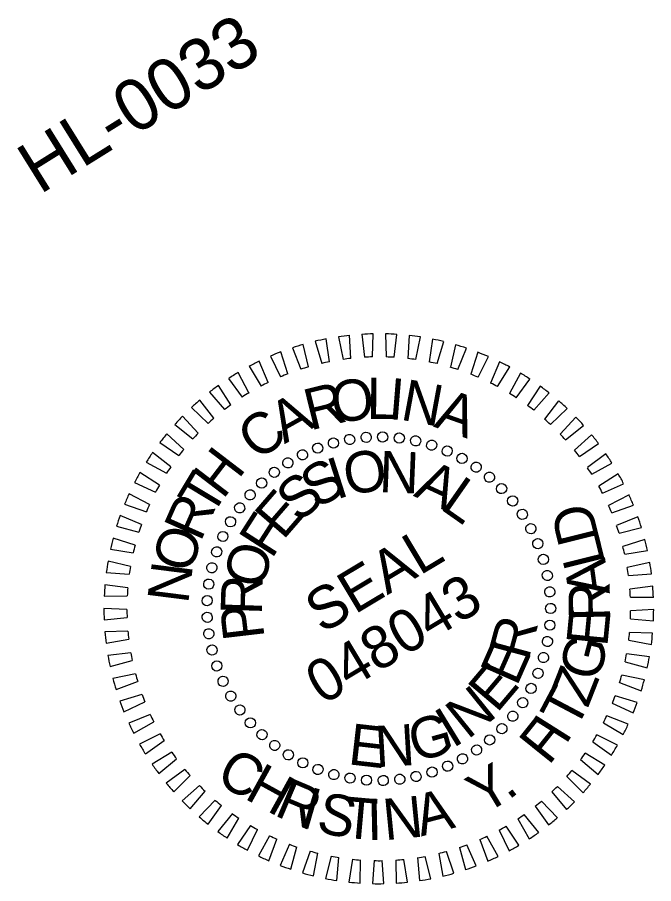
# Model space of a CAD drawing. Extents: x 2045918 to 2047994, y 757573 to 759227.
# Drawn here: x 2047092.2 to 2047184.8, y 759053.8 to 759179.9 of the extents above; entities that cross this region are included whole.
import ezdxf

# ---------------------------------------------------------------- set-up
doc = ezdxf.new("R2010")
doc.units = 0
doc.layers.add('Sheet Data Field CELL', color=7, linetype='Continuous')
doc.layers.add('Sheet PE Seal Cell', color=7, linetype='Continuous')

msp = doc.modelspace()

# ---------------------------------------------------------------- linework, layer by layer
at = {"layer": 'Sheet PE Seal Cell'}
for p, q in [((2047138.94, 759133.41), (2047139.61, 759130.12)), ((2047140.75, 759130.27), (2047140.57, 759133.62)), ((2047142.36, 759133.77), (2047142.74, 759130.44)), ((2047143.89, 759130.48), (2047144.01, 759133.84)), ((2047145.8, 759133.83), (2047145.9, 759130.48)), ((2047147.05, 759130.43), (2047147.45, 759133.76)), ((2047149.23, 759133.6), (2047149.04, 759130.25)), ((2047150.18, 759130.1), (2047150.87, 759133.38)), ((2047134.57, 759129.03), (2047133.82, 759132.31)), ((2047135.56, 759132.76), (2047136.51, 759129.54)), ((2047137.63, 759129.78), (2047137.17, 759133.11)), ((2047152.63, 759133.07), (2047152.16, 759129.75)), ((2047153.28, 759129.5), (2047154.25, 759132.71)), ((2047155.98, 759132.25), (2047155.22, 759128.99)), ((2047131.58, 759128.02), (2047130.56, 759131.22)), ((2047132.24, 759131.82), (2047133.47, 759128.7)), ((2047156.31, 759128.64), (2047157.55, 759131.76)), ((2047159.24, 759131.15), (2047158.2, 759127.96)), ((2047128.69, 759126.76), (2047127.4, 759129.85)), ((2047129.03, 759130.6), (2047130.52, 759127.59)), ((2047159.26, 759127.52), (2047160.76, 759130.52)), ((2047162.39, 759129.77), (2047161.08, 759126.68)), ((2047125.93, 759129.11), (2047127.67, 759126.24)), ((2047162.1, 759126.16), (2047163.86, 759129.02)), ((2047122.96, 759127.35), (2047124.95, 759124.64)), ((2047125.92, 759125.25), (2047124.36, 759128.22)), ((2047165.42, 759128.13), (2047163.84, 759125.16)), ((2047164.82, 759124.55), (2047166.81, 759127.25)), ((2047123.29, 759123.51), (2047121.48, 759126.34)), ((2047168.29, 759126.23), (2047166.47, 759123.41)), ((2047120.16, 759125.35), (2047122.37, 759122.82)), ((2047167.38, 759122.72), (2047169.6, 759125.23)), ((2047120.82, 759121.55), (2047118.78, 759124.21)), ((2047170.98, 759124.09), (2047168.93, 759121.44)), ((2047117.55, 759123.11), (2047119.96, 759120.79)), ((2047169.78, 759120.67), (2047172.21, 759122.99)), ((2047118.53, 759119.39), (2047116.26, 759121.86)), ((2047173.49, 759121.73), (2047171.21, 759119.26)), ((2047115.13, 759120.66), (2047117.74, 759118.55)), ((2047172, 759118.42), (2047174.61, 759120.52)), ((2047116.43, 759117.03), (2047113.96, 759119.31)), ((2047175.78, 759119.16), (2047173.3, 759116.9)), ((2047112.94, 759118.01), (2047115.72, 759116.13)), ((2047174.01, 759115.99), (2047176.8, 759117.86)), ((2047114.54, 759114.51), (2047111.89, 759116.56)), ((2047177.84, 759116.4), (2047175.17, 759114.37)), ((2047110.98, 759115.18), (2047113.91, 759113.55)), ((2047175.8, 759113.4), (2047178.74, 759115.02)), ((2047112.88, 759111.83), (2047110.05, 759113.65)), ((2047179.66, 759113.48), (2047176.83, 759111.68)), ((2047109.27, 759112.2), (2047112.33, 759110.82)), ((2047177.37, 759110.67), (2047180.44, 759112.03)), ((2047111.45, 759109.02), (2047108.48, 759110.58)), ((2047181.22, 759110.41), (2047178.24, 759108.86)), ((2047107.82, 759109.07), (2047110.99, 759107.96)), ((2047178.7, 759107.8), (2047181.87, 759108.9)), ((2047110.27, 759106.09), (2047107.18, 759107.4)), ((2047182.51, 759107.22), (2047179.41, 759105.93)), ((2047106.65, 759105.84), (2047109.9, 759105)), ((2047179.77, 759104.84), (2047183.03, 759105.66)), ((2047109.34, 759103.08), (2047106.15, 759104.11)), ((2047183.52, 759103.93), (2047180.32, 759102.91)), ((2047105.76, 759102.51), (2047109.07, 759101.96)), ((2047180.59, 759101.79), (2047183.9, 759102.33)), ((2047108.68, 759100), (2047105.41, 759100.75)), ((2047184.24, 759100.57), (2047180.97, 759099.83)), ((2047105.16, 759099.12), (2047108.5, 759098.86)), ((2047181.14, 759098.69), (2047184.48, 759098.94)), ((2047108.28, 759096.87), (2047104.96, 759097.34)), ((2047184.67, 759097.15), (2047181.35, 759096.7)), ((2047104.85, 759095.69), (2047108.21, 759095.72)), ((2047181.42, 759095.55), (2047184.77, 759095.51)), ((2047108.16, 759093.72), (2047104.81, 759093.9)), ((2047144.81, 759093.84), (2047144.81, 759093.84)), ((2047184.81, 759093.71), (2047181.46, 759093.54)), ((2047104.84, 759092.25), (2047108.18, 759092.57)), ((2047181.43, 759092.39), (2047184.77, 759092.06)), ((2047108.31, 759090.57), (2047104.95, 759090.46)), ((2047105.13, 759088.82), (2047108.43, 759089.42)), ((2047181.17, 759089.25), (2047184.47, 759088.64)), ((2047184.65, 759090.28), (2047181.3, 759090.39)), ((2047108.72, 759087.44), (2047105.39, 759087.05)), ((2047184.2, 759086.86), (2047180.86, 759087.27)), ((2047105.7, 759085.43), (2047108.94, 759086.31)), ((2047180.64, 759086.14), (2047183.87, 759085.25)), ((2047109.41, 759084.36), (2047106.12, 759083.69)), ((2047106.57, 759082.1), (2047109.72, 759083.26)), ((2047179.85, 759083.09), (2047182.99, 759081.92)), ((2047183.45, 759083.5), (2047180.17, 759084.2)), ((2047110.35, 759081.35), (2047107.14, 759080.4)), ((2047182.42, 759080.22), (2047179.21, 759081.19)), ((2047107.72, 759078.86), (2047110.76, 759080.28)), ((2047178.79, 759080.12), (2047181.82, 759078.68)), ((2047111.55, 759078.44), (2047108.43, 759077.21)), ((2047181.11, 759077.04), (2047177.99, 759078.28)), ((2047109.15, 759075.72), (2047112.05, 759077.4)), ((2047177.49, 759077.25), (2047180.38, 759075.56)), ((2047113, 759075.64), (2047110, 759074.14)), ((2047179.53, 759073.98), (2047176.53, 759075.49)), ((2047110.84, 759072.73), (2047113.59, 759074.65)), ((2047175.94, 759074.5), (2047178.68, 759072.56)), ((2047114.68, 759072.97), (2047111.82, 759071.22)), ((2047112.78, 759069.88), (2047115.35, 759072.03)), ((2047174.16, 759071.9), (2047176.72, 759069.73)), ((2047177.69, 759071.07), (2047174.83, 759072.83)), ((2047116.59, 759070.46), (2047113.89, 759068.47)), ((2047114.96, 759067.22), (2047117.34, 759069.58)), ((2047172.17, 759069.45), (2047174.53, 759067.08)), ((2047175.61, 759068.33), (2047172.92, 759070.32)), ((2047118.71, 759068.12), (2047116.18, 759065.91)), ((2047173.3, 759065.77), (2047170.79, 759067.99)), ((2047117.36, 759064.75), (2047119.53, 759067.31)), ((2047169.97, 759067.19), (2047172.12, 759064.62)), ((2047121.01, 759065.97), (2047118.69, 759063.55)), ((2047170.79, 759063.43), (2047168.47, 759065.86)), ((2047119.96, 759062.5), (2047121.9, 759065.24)), ((2047167.58, 759065.13), (2047169.51, 759062.38)), ((2047123.5, 759064.03), (2047121.39, 759061.42)), ((2047122.75, 759060.48), (2047124.44, 759063.37)), ((2047165.03, 759063.28), (2047166.71, 759060.37)), ((2047168.08, 759061.31), (2047165.98, 759063.93)), ((2047126.14, 759062.31), (2047124.26, 759059.52)), ((2047125.7, 759058.71), (2047127.14, 759061.73)), ((2047162.33, 759061.65), (2047163.76, 759058.62)), ((2047165.19, 759059.43), (2047163.33, 759062.22)), ((2047128.92, 759060.82), (2047127.29, 759057.88)), ((2047128.79, 759057.19), (2047129.96, 759060.33)), ((2047159.5, 759060.27), (2047160.66, 759057.12)), ((2047162.16, 759057.8), (2047160.54, 759060.74)), ((2047131.82, 759059.57), (2047130.45, 759056.51)), ((2047132, 759055.95), (2047132.9, 759059.18)), ((2047156.55, 759059.13), (2047157.44, 759055.89)), ((2047159, 759056.44), (2047157.64, 759059.51)), ((2047134.81, 759058.58), (2047133.71, 759055.41)), ((2047135.3, 759054.99), (2047135.92, 759058.29)), ((2047137.88, 759057.85), (2047137.05, 759054.6)), ((2047152.38, 759054.57), (2047151.57, 759057.82)), ((2047153.53, 759058.25), (2047154.13, 759054.95)), ((2047155.73, 759055.36), (2047154.64, 759058.54)), ((2047138.68, 759054.32), (2047139.01, 759057.66)), ((2047141, 759057.39), (2047140.46, 759054.08)), ((2047142.1, 759053.94), (2047142.15, 759057.29)), ((2047144.15, 759057.2), (2047143.89, 759053.85)), ((2047145.54, 759053.85), (2047145.3, 759057.2)), ((2047147.3, 759057.28), (2047147.33, 759053.92)), ((2047148.97, 759054.06), (2047148.45, 759057.37)), ((2047150.43, 759057.63), (2047150.75, 759054.29))]:
    msp.add_line(p, q, dxfattribs=at)
for radius, start, end in [(40, 96.0801, 98.4437), (40, 91.1486, 93.5122), (40, 86.2171, 88.5807), (40, 81.2856, 83.6492), (40, 105.9431, 108.3067), (40, 101.0116, 103.3752), (40, 76.3541, 78.7177), (40, 71.4226, 73.7862), (40, 110.8746, 113.2382), (40, 66.491, 68.8547), (40, 115.8061, 118.1697), (36.65, 101.2945, 103.0924), (36.65, 96.363, 98.1608), (36.65, 91.4314, 93.2293), (36.65, 86.4999, 88.2978), (36.65, 81.5684, 83.3663), (36.65, 76.6369, 78.4348), (40, 61.5595, 63.9232), (36.65, 106.226, 108.0239), (36.65, 71.7054, 73.5033), (40, 120.7376, 123.1012), (36.65, 111.1575, 112.9554), (36.65, 66.7739, 68.5718), (40, 56.628, 58.9917), (40, 125.6691, 128.0327), (36.65, 116.089, 117.8869), (36.65, 61.8424, 63.6403), (40, 51.6965, 54.0601), (36.65, 121.0205, 122.8184), (36.65, 56.9109, 58.7088), (40, 130.6006, 132.9643), (36.65, 125.952, 127.7499), (36.65, 51.9794, 53.7773), (40, 46.765, 49.1286), (40, 135.5321, 137.8958), (36.65, 130.8835, 132.6814), (36.65, 47.0479, 48.8458), (40, 41.8335, 44.1971), (40, 140.4637, 142.8273), (36.65, 135.815, 137.6129), (36.65, 42.1164, 43.9143), (40, 36.902, 39.2656), (36.65, 140.7465, 142.5444), (40, 145.3952, 147.7588), (36.65, 37.1849, 38.9828), (40, 31.9705, 34.3341), (36.65, 145.678, 147.4759), (40, 150.3267, 152.6903), (36.65, 32.2534, 34.0513), (40, 27.039, 29.4026), (36.65, 150.6095, 152.4074), (36.65, 27.3219, 29.1197), (40, 155.2582, 157.6218), (40, 22.1075, 24.4711), (36.65, 155.541, 157.3389), (36.65, 22.3903, 24.1882), (40, 160.1897, 162.5533), (40, 17.176, 19.5396), (36.65, 160.4725, 162.2704), (36.65, 17.4588, 19.2567), (40, 165.1212, 167.4848), (40, 12.2445, 14.6081), (36.65, 165.404, 167.2019), (36.65, 12.5273, 14.3252), (40, 170.0527, 172.4163), (36.65, 170.3356, 172.1334), (36.65, 7.5958, 9.3937), (40, 7.313, 9.6766), (40, 174.9842, 177.3478), (36.65, 175.2671, 177.065), (40, 2.3815, 4.7451), (36.65, 2.6643, 4.4622), (40, 179.9157, 182.2793), (36.65, 180.1986, 181.9965), (36.65, 357.7328, 359.5307), (40, 357.45, 359.8136), (36.65, 185.1301, 186.928), (40, 184.8472, 187.2108), (36.65, 352.8013, 354.5992), (40, 352.5184, 354.8821), (40, 189.7787, 192.1423), (36.65, 190.0616, 191.8595), (36.65, 347.8698, 349.6677), (40, 347.5869, 349.9506), (36.65, 194.9931, 196.791), (40, 194.7102, 197.0738), (36.65, 342.9383, 344.7362), (40, 342.6554, 345.019), (36.65, 199.9246, 201.7225), (36.65, 338.0068, 339.8047), (40, 199.6417, 202.0054), (40, 337.7239, 340.0875), (36.65, 204.8561, 206.654), (36.65, 333.0753, 334.8732), (40, 204.5732, 206.9369), (40, 332.7924, 335.156), (36.65, 209.7876, 211.5855), (36.65, 328.1438, 329.9417), (40, 209.5047, 211.8684), (36.65, 214.7191, 216.517), (40, 327.8609, 330.2245), (36.65, 323.2123, 325.0102), (40, 214.4363, 216.7999), (36.65, 219.6506, 221.4485), (40, 322.9294, 325.293), (36.65, 318.2808, 320.0787), (40, 219.3678, 221.7314), (36.65, 224.5821, 226.38), (36.65, 313.3493, 315.1471), (40, 317.9979, 320.3615), (40, 224.2993, 226.6629), (36.65, 229.5136, 231.3115), (36.65, 308.4177, 310.2156), (40, 313.0664, 315.43), (40, 229.2308, 231.5944), (36.65, 234.4451, 236.243), (36.65, 303.4862, 305.2841), (40, 308.1349, 310.4985), (36.65, 239.3766, 241.1745), (36.65, 298.5547, 300.3526), (40, 234.1623, 236.5259), (36.65, 244.3082, 246.1061), (36.65, 293.6232, 295.4211), (40, 303.2034, 305.567), (40, 239.0938, 241.4574), (36.65, 249.2397, 251.0376), (36.65, 288.6917, 290.4896), (40, 298.2719, 300.6355), (40, 244.0253, 246.3889), (36.65, 254.1712, 255.9691), (36.65, 259.1027, 260.9006), (36.65, 278.8287, 280.6266), (36.65, 283.7602, 285.5581), (40, 293.3404, 295.704), (40, 248.9568, 251.3204), (36.65, 264.0342, 265.8321), (36.65, 268.9657, 270.7636), (36.65, 273.8972, 275.6951), (40, 253.8883, 256.2519), (40, 283.4773, 285.841), (40, 288.4089, 290.7725), (40, 258.8198, 261.1834), (40, 263.7513, 266.1149), (40, 273.6143, 275.978), (40, 278.5458, 280.9095), (40, 268.6828, 271.0464)]:
    msp.add_arc((2047144.81, 759093.84), radius, start, end, dxfattribs=at)
for centre, major_axis in [((2047142.97, 759118.78), (-0.106, 0.735)), ((2047145.38, 759118.84), (-0.035, 0.742)), ((2047138.21, 759117.96), (-0.245, 0.701)), ((2047140.57, 759118.48), (-0.177, 0.721)), ((2047147.79, 759118.67), (0.037, 0.741)), ((2047150.17, 759118.26), (0.108, 0.734)), ((2047152.5, 759117.63), (0.179, 0.721)), ((2047133.7, 759116.24), (-0.375, 0.64)), ((2047135.91, 759117.21), (-0.312, 0.674)), ((2047154.76, 759116.78), (0.247, 0.7)), ((2047131.59, 759115.06), (-0.435, 0.601)), ((2047156.93, 759115.71), (0.314, 0.673)), ((2047129.6, 759113.69), (-0.491, 0.556)), ((2047158.98, 759114.44), (0.377, 0.639)), ((2047160.91, 759112.97), (0.437, 0.6)), ((2047127.76, 759112.13), (-0.543, 0.506)), ((2047162.68, 759111.33), (0.493, 0.555)), ((2047126.08, 759110.4), (-0.589, 0.452)), ((2047164.28, 759109.52), (0.544, 0.505)), ((2047124.56, 759108.51), (-0.63, 0.393)), ((2047165.7, 759107.57), (0.59, 0.45)), ((2047123.24, 759106.49), (-0.665, 0.33)), ((2047166.93, 759105.49), (0.631, 0.391)), ((2047122.12, 759104.35), (-0.694, 0.264)), ((2047167.95, 759103.3), (0.666, 0.328)), ((2047121.22, 759102.11), (-0.716, 0.196)), ((2047168.76, 759101.02), (0.694, 0.262)), ((2047120.53, 759099.8), (-0.732, 0.126)), ((2047169.34, 759098.68), (0.717, 0.194)), ((2047120.07, 759097.42), (-0.74, 0.055)), ((2047169.69, 759096.29), (0.732, 0.124)), ((2047119.84, 759095.02), (-0.742, -0.017)), ((2047169.81, 759093.88), (0.74, 0.053)), ((2047119.84, 759092.6), (-0.737, -0.088)), ((2047169.7, 759091.46), (0.742, -0.019)), ((2047120.08, 759090.2), (-0.725, -0.159)), ((2047169.35, 759089.07), (0.737, -0.091)), ((2047120.54, 759087.83), (-0.706, -0.228)), ((2047168.77, 759086.73), (0.725, -0.161)), ((2047121.24, 759085.52), (-0.681, -0.296)), ((2047167.98, 759084.45), (0.706, -0.23)), ((2047122.15, 759083.28), (-0.649, -0.36)), ((2047166.96, 759082.25), (0.68, -0.297)), ((2047123.28, 759081.14), (-0.612, -0.421)), ((2047165.74, 759080.17), (0.648, -0.362)), ((2047124.6, 759079.12), (-0.568, -0.478)), ((2047126.12, 759077.24), (-0.519, -0.53)), ((2047164.32, 759078.21), (0.61, -0.423)), ((2047162.72, 759076.4), (0.567, -0.479)), ((2047127.81, 759075.52), (-0.466, -0.578)), ((2047160.95, 759074.76), (0.518, -0.532)), ((2047129.66, 759073.96), (-0.408, -0.62)), ((2047131.65, 759072.59), (-0.346, -0.657)), ((2047159.04, 759073.29), (0.464, -0.579)), ((2047133.76, 759071.42), (-0.281, -0.687)), ((2047154.82, 759070.94), (0.344, -0.658)), ((2047156.99, 759072.01), (0.406, -0.622)), ((2047135.97, 759070.46), (-0.213, -0.711)), ((2047138.27, 759069.71), (-0.144, -0.728)), ((2047152.56, 759070.08), (0.279, -0.688)), ((2047140.63, 759069.2), (-0.073, -0.739)), ((2047143.03, 759068.91), (-0.001, -0.742)), ((2047145.45, 759068.85), (0.071, -0.739)), ((2047147.85, 759069.03), (0.142, -0.729)), ((2047150.23, 759069.44), (0.211, -0.712))]:
    msp.add_ellipse(centre, major_axis=major_axis, ratio=0.999708, dxfattribs=at)

# ---------------------------------------------------------------- texts
at = {"layer": 'Sheet Data Field CELL'}
msp.add_text('HL-0033', height=7.5, rotation=31.918, dxfattribs=at).set_placement((2047095.48, 759154.03))
at = {"layer": 'Sheet PE Seal Cell'}
for s, height, rotation, p in [('O', 6, 6.5508, (2047138.2, 759120.86)), ('L', 6, 359.3506, (2047143, 759121.47)), ('I', 6, 355.3629, (2047146.08, 759121.45)), ('N', 6, 349.5264, (2047147.81, 759121.38)), ('R', 6, 13.8401, (2047134.81, 759119.76)), ('A', 6, 340.5961, (2047152.68, 759120.35)), ('A', 6, 29.3273, (2047131.08, 759117.77)), ('C', 6, 38.2117, (2047127.31, 759115.19)), ('H', 6, 52.5806, (2047122.12, 759109.63)), ('I', 6, 17.7649, (2047138.62, 759109.7)), ('O', 6, 9.375, (2047140.19, 759110.31)), ('N', 6, 357.6615, (2047144.77, 759110.83)), ('S', 6, 31.9248, (2047135.88, 759108.26)), ('A', 6, 335.1412, (2047149.73, 759110.29)), ('T', 6, 58.9737, (2047120.48, 759106.99)), ('S', 6, 40.305, (2047133.14, 759106.23)), ('L', 6, 325.0081, (2047153.56, 759108.47)), ('E', 6, 49.1041, (2047130.87, 759103.71)), ('R', 6, 66.0707, (2047118.86, 759103.45)), ('D', 6, 103.9715, (2047176.94, 759103.98)), ('F', 6, 57.3313, (2047129.22, 759100.96)), ('O', 6, 73.7333, (2047117.5, 759098.83)), ('SEAL', 6.184, 30.9194, (2047136.57, 759090.12)), ('L', 6, 103.9715, (2047177.8, 759100.55)), ('O', 6, 76.279, (2047127.99, 759096.57)), ('A', 6, 97.8553, (2047178.45, 759096.06)), ('N', 6, 82.753, (2047117.06, 759094.45)), ('R', 6, 88.2053, (2047127.77, 759092.87)), ('048043', 6.185, 30.9194, (2047136.65, 759079.77)), ('R', 6, 91.033, (2047178.48, 759092.05)), ('P', 6, 96.7125, (2047128.21, 759089.61)), ('E', 6, 84.4584, (2047178.05, 759088.2)), ('R', 6, 74.9171, (2047166.56, 759086.16)), ('E', 6, 66.1641, (2047164.88, 759082.42)), ('G', 6, 75.4678, (2047176.76, 759083.08)), ('E', 6, 49.7605, (2047161.98, 759078.54)), ('Z', 6, 68.5009, (2047175.21, 759079.28)), ('T', 6, 62.1328, (2047173.41, 759076)), ('N', 6, 38.9112, (2047157.74, 759074.72)), ('I', 6, 31.4617, (2047155.54, 759073.47)), ('G', 6, 15.877, (2047150.14, 759071.47)), ('F', 6, 51.2551, (2047169.52, 759070.92)), ('I', 6, 57.7677, (2047171.97, 759073.87)), ('E', 6, 353.4938, (2047140.21, 759071.23)), ('N', 6, 3.3473, (2047144.41, 759070.78)), ('C', 6, 331.1555, (2047120.86, 759068.64)), ('H', 6, 331.1555, (2047125.09, 759066.31)), ('Y', 6, 30.9841, (2047160.05, 759063.78)), ('R', 6, 336.9833, (2047129.43, 759063.84)), ('I', 6, 343.8057, (2047133.11, 759062.23)), ('S', 6, 348.1708, (2047135.55, 759061.43)), ('N', 6, 5.6231, (2047145.7, 759060.15)), ('A', 6, 14.6137, (2047150.95, 759060.7)), ('.', 6, 38.0956, (2047163.65, 759065.9)), ('T', 6, 354.8899, (2047139.4, 759060.57)), ('I', 6, 1.258, (2047143.13, 759060.18))]:
    msp.add_text(s, height=height, rotation=rotation, dxfattribs=at).set_placement(p)

doc.saveas('drawing.dxf')
